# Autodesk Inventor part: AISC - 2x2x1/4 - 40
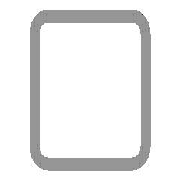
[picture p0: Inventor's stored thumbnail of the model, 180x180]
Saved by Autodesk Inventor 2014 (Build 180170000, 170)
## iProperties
IsCustomPart: 1
Created: 2013-02
Part Number: AISC - 2x2x1/4 - 40
Material: Steel, Mild
Description: Tube
Document SubType Name: Modeling
Standard: AISC
Designer: Dave Walker
Standards Organization: ANSI
Language: en-US
Size Designation: 2x2x1/4 - 40
Categories: <MemberInstance><Categories><Category DisplayName="Structural Shapes" InternalName="089c4875-fa83-4c05-b084-43b9cc11f5ed" Mnemonic="GRDR"><CategoryParameter Dis
Stock Number: 2x2x1/4
Density: 1 g/cm^3
Appearance: Steel
G_L: 44.000 in
Author: Dave Walker
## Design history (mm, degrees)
node "Start plane"
node "End plane"
sketch "Sketch"
  geometry: L1 (-25.4, -12.7)-(-25.4, 12.7); L2 (-12.7, 25.4)-(12.7, 25.4); L3 (25.4, 12.7)-(25.4, -12.7); L4 (12.7, -25.4)-(-12.7, -25.4); L5 (-12.7, 19.05)-(12.7, 19.05); L6 (19.05, 12.7)-(19.05, -12.7); L7 (12.7, -19.05)-(-12.7, -19.05); L8 (-19.05, -12.7)-(-19.05, 12.7); L9 (0, 39.242)-(0, -39.242) reference; L10 (-39.242, 0)-(39.242, 0) reference; A1 r 12.7 centre (-12.7, -12.7) between (-25.4, -12.7) and (-12.7, -25.4); A2 r 12.7 centre (-12.7, 12.7) between (-12.7, 25.4) and (-25.4, 12.7); A3 r 12.7 centre (12.7, 12.7) between (25.4, 12.7) and (12.7, 25.4); A4 r 12.7 centre (12.7, -12.7) between (12.7, -25.4) and (25.4, -12.7); A5 r 6.35 centre (-12.7, 12.7) between (-12.7, 19.05) and (-19.05, 12.7); A6 r 6.35 centre (12.7, 12.7) between (19.05, 12.7) and (12.7, 19.05); A7 r 6.35 centre (12.7, -12.7) between (12.7, -19.05) and (19.05, -12.7); A8 r 6.35 centre (-12.7, -12.7) between (-19.05, -12.7) and (-12.7, -19.05)
  constraints: 16 end point, 16 point on circle, 8 centre point, 8 tangent, 4 parallel, 3 equal radius, 2 perpendicular, 7 other
  dimensions: "d10" = 50.8 distance between parallel lines of L2 L4 (= G_H); "d11" = 50.8 distance between parallel lines of L1 L3 (= G_W); "d12" = 6.35 distance between parallel lines of L3 L6 (= G_T); "d15" = 25.4 distance between parallel lines of L2 L10 (= 0.5 x d10); "d16" = 25.4 distance between parallel lines of L9 L3 (= 0.5 x d11); "d17" = 12.7 radius of A1 (= G_IR)
extrude "Body" new body sketch "Sketch" stored distance "d3" = 1117.6 (= G_L); taper "d4" = 0 deg
node "Driven Length"
  sketch "Sketch3"
    geometry: L1 (0, 0)-(10, 0) reference
    constraints: 2 end point, 1 horizontal
  workplane "Work Plane3"
  sketch "Sketch4"
    geometry: L1 (-2, 0)-(12, 0) reference; L2 (-2, 1117.6)-(12, 1117.6) reference
    dimensions: "d19" = 1117.6 distance between parallel lines of L1 L2 (derived)
body "Solid1"
other parameters: "G_W" = 50.8 [user parameter; used in 1 equation term], "G_H" = 50.8 [user parameter; used in 1 equation term], "G_T" = 6.35 [user parameter; used in 1 equation term], "G_IR" = 12.7 [user parameter; used in 1 equation term], "G_L" = 1117.6 (= d19) [user parameter; used in 1 equation term], "G_OFFSET_START" = 0 [user parameter; used in 1 equation term], "G_OFFSET_END" = 0 [user parameter], "d13" = 0 (computed from G_OFFSET_START), "d14" = 1117.6, "B_L" = 1016 [user parameter], "d18" = 90 deg
